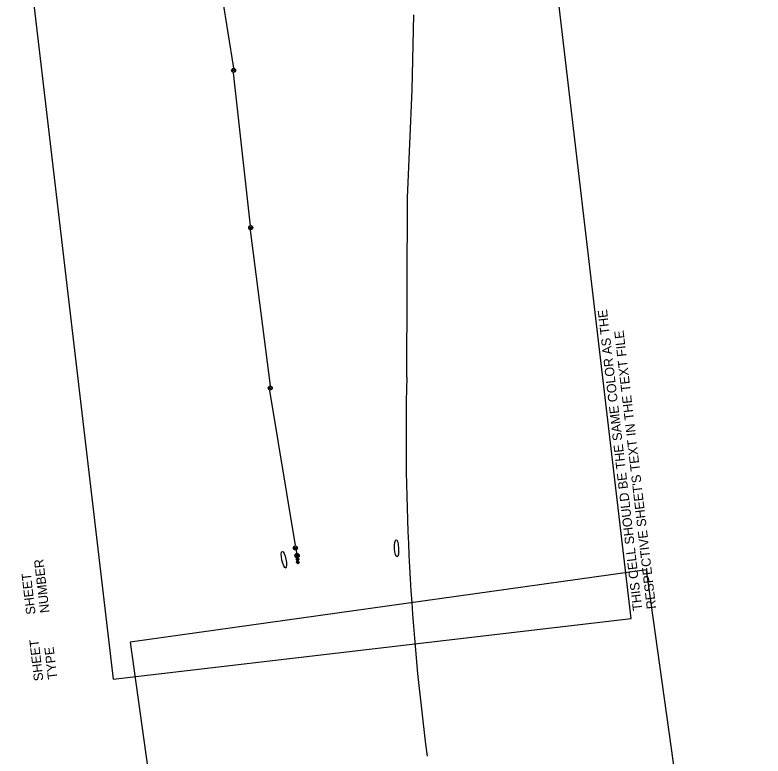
# Model space of a CAD drawing. Extents: x 601462 to 605493, y 331960 to 402715.
# Drawn here: x 602354 to 603753, y 385925 to 387311 of the extents above; entities that cross this region are included whole.
import ezdxf

# ---------------------------------------------------------------- set-up
doc = ezdxf.new("R2010")
doc.units = 0
for name, color, linetype in [('P_FTMS', 7, 'Continuous'), ('P_FTMSConduit', 7, 'Continuous'), ('P_MISC_TXT_1A (Construction)', 7, 'Continuous'), ('P_MISC_TXT_1B (Construction)', 7, 'Continuous')]:
    doc.layers.add(name, color=color, linetype=linetype)

# ---------------------------------------------------------------- blocks, each defined once
blk = doc.blocks.new('_U231')
at = {"layer": 'P_FTMS'}
for p, q in [((12.1, 1.6), (-12.2, -0.1)), ((11.8, 3), (-12.1, 1.4)), ((11.9, 2.3), (-12.1, 0.6)), ((12.1, 0.8), (-12.1, -0.8)), ((12.1, 0.1), (-12.1, -1.6)), ((11.6, 3.7), (-12, 2.1)), ((-11.9, 2.5), (-11.4, -4.2)), ((11.3, 4.4), (-11.8, 2.9)), ((11, 5.2), (-11.6, 3.6)), ((10.6, 5.9), (-11.4, 4.4)), ((-11.3, 4.5), (-10.6, -6)), ((10.2, 6.6), (-11, 5.1)), ((9.8, 7.3), (-10.7, 5.9)), ((-10.7, 5.9), (-9.8, -7.2)), ((9.2, 8), (-10.2, 6.6)), ((-10, 6.9), (-9, -8.2)), ((8.6, 8.6), (-9.7, 7.4)), ((-9.3, 7.8), (-8.2, -9)), ((7.8, 9.3), (-9, 8.2)), ((-8.6, 8.5), (-7.4, -9.6)), ((6.9, 10), (-8.2, 9)), ((-8, 9.2), (-6.6, -10.2)), ((-7.3, 9.7), (-5.9, -10.6)), ((5.8, 10.7), (-7.2, 9.8)), ((-6.6, 10.3), (-5.1, -11)), ((4.5, 11.3), (-6, 10.6)), ((-5.9, 10.7), (-4.4, -11.4)), ((-5.1, 11), (-3.6, -11.6)), ((-4.4, 11.3), (-2.9, -11.8)), ((2.5, 11.9), (-4.1, 11.5)), ((-3.7, 11.6), (-2.1, -12)), ((-3, 11.8), (-1.4, -12.1)), ((-2.3, 12), (-0.6, -12.2)), ((-1.6, 12.1), (0.1, -12.2)), ((-0.8, 12.1), (0.8, -12.1)), ((-0.1, 12.2), (1.6, -12.1)), ((0.6, 12.1), (2.3, -11.9)), ((1.4, 12.1), (3, -11.8)), ((2.1, 12), (3.7, -11.6)), ((2.9, 11.8), (4.4, -11.3)), ((3.6, 11.6), (5.1, -11)), ((4.4, 11.3), (5.9, -10.7)), ((5.1, 11), (6.6, -10.2)), ((5.9, 10.6), (7.3, -9.8)), ((6.6, 10.2), (8, -9.2)), ((7.4, 9.7), (8.6, -8.6)), ((8.2, 9), (9.3, -7.8)), ((9, 8.2), (10, -6.9)), ((9.8, 7.2), (10.7, -5.8)), ((10.6, 5.9), (11.3, -4.5)), ((11.5, 4), (11.9, -2.5)), ((12.1, -0.6), (-12, -2.3)), ((12.1, -1.4), (-11.8, -3)), ((12, -2.1), (-11.6, -3.7)), ((11.8, -2.9), (-11.3, -4.4)), ((11.6, -3.6), (-11, -5.1)), ((11.3, -4.4), (-10.7, -5.9)), ((11.1, -5.1), (-10.2, -6.6)), ((10.6, -5.9), (-9.8, -7.3)), ((10.2, -6.6), (-9.2, -8)), ((9.6, -7.4), (-8.5, -8.6)), ((9, -8.2), (-7.8, -9.3)), ((8.2, -9), (-6.9, -10)), ((7.3, -9.8), (-5.8, -10.7)), ((6, -10.6), (-4.5, -11.3)), ((4.1, -11.5), (-2.6, -11.9))]:
    blk.add_line(p, q, dxfattribs=at)
blk.add_circle((0, 0), 12.2, dxfattribs=at)
blk = doc.blocks.new('FMD')
at = {"layer": 'P_FTMS'}
for p, q in [((16.9, 17.6), (-16.9, 17.6)), ((-16.1, 16.1), (-16.1, 18.4)), ((16.1, 16.1), (-16.1, 16.1)), ((15.5, 19), (-15.5, 19)), ((-14.6, 14.6), (-14.6, 19.9)), ((14.6, 14.6), (-14.6, 14.6)), ((14, 20.5), (-14, 20.5)), ((-13.2, 13.2), (-13.2, 21.3)), ((13.2, 13.2), (-13.2, 13.2)), ((12.5, 21.9), (-12.5, 21.9)), ((-11.7, 11.7), (-11.7, 22.8)), ((11.7, 11.7), (-11.7, 11.7)), ((11.1, 23.4), (-11.1, 23.4)), ((-10.2, 10.2), (-10.2, 24.2)), ((10.2, 10.2), (-10.2, 10.2)), ((9.6, 24.9), (-9.6, 24.9)), ((-8.8, 8.8), (-8.8, 25.7)), ((8.8, 8.8), (-8.8, 8.8)), ((8.2, 26.3), (-8.2, 26.3)), ((-7.3, 7.3), (-7.3, 27.2)), ((7.3, 7.3), (-7.3, 7.3)), ((6.7, 27.8), (-6.7, 27.8)), ((-5.9, 5.9), (-5.9, 28.6)), ((5.9, 5.9), (-5.9, 5.9)), ((5.2, 29.3), (-5.2, 29.3)), ((-4.4, 4.4), (-4.4, 30.1)), ((4.4, 4.4), (-4.4, 4.4)), ((3.8, 30.7), (-3.8, 30.7)), ((-2.9, 2.9), (-2.9, 31.6)), ((2.9, 2.9), (-2.9, 2.9)), ((2.3, 32.2), (-2.3, 32.2)), ((-1.5, 1.5), (-1.5, 33)), ((1.5, 1.5), (-1.5, 1.5)), ((0.8, 33.6), (-0.8, 33.6)), ((0, 0), (0, 34.5)), ((1.5, 1.5), (1.5, 33)), ((2.9, 2.9), (2.9, 31.6)), ((4.4, 4.4), (4.4, 30.1)), ((5.9, 5.9), (5.9, 28.6)), ((7.3, 7.3), (7.3, 27.2)), ((8.8, 8.8), (8.8, 25.7)), ((10.2, 10.2), (10.2, 24.2)), ((11.7, 11.7), (11.7, 22.8)), ((13.2, 13.2), (13.2, 21.3)), ((14.6, 14.6), (14.6, 19.9)), ((16.1, 16.1), (16.1, 18.4))]:
    blk.add_line(p, q, dxfattribs=at)
blk.add_lwpolyline([(-17.2, 17.2), (0, 34.5), (17.2, 17.2), (0, 0)], close=True, dxfattribs=at)

msp = doc.modelspace()

# ---------------------------------------------------------------- linework, layer by layer
at = {"layer": 'P_FTMS'}
for centre in [(602763.2, 387207.5), (602795.1, 386913.4), (602831.5, 386613.3), (602878.6, 386314.3)]:
    msp.add_circle(centre, 3.75, dxfattribs=at)
for centre, start, end in [((602762.8, 387203), 32.6299, 138.8855), ((602763.5, 387212), 212.6299, 318.8855), ((602794.8, 386908.9), 32.6299, 138.8855), ((602795.5, 386917.9), 212.6299, 318.8855), ((602831.1, 386608.8), 32.6299, 138.8855), ((602831.8, 386617.8), 212.6299, 318.8855), ((602878.2, 386309.8), 32.6299, 138.8855), ((602878.9, 386318.8), 212.6299, 318.8855)]:
    msp.add_arc(centre, 3.75, start, end, dxfattribs=at)
for centre, major_axis in [((603067.9, 386313.7), (-0.9, 16)), ((602857.2, 386292.3), (-3.3, 15.6))]:
    msp.add_ellipse(centre, major_axis=major_axis, ratio=0.23471, dxfattribs=at)
at = {"layer": 'P_FTMSConduit'}
for p, q in [((602763.5, 387212), (602715.8, 387506.6)), ((602794.8, 386917.1), (602762.8, 387203)), ((602831.8, 386617.8), (602794.8, 386908.9)), ((602878.9, 386318.8), (602831.1, 386608.8)), ((602881.3, 386303.9), (602880.4, 386311))]:
    msp.add_line(p, q, dxfattribs=at)
msp.add_lwpolyline([(603086.8, 386633.3), (603088.1, 386969), (603097.2, 387171.1), (603099.9, 387311.3)], dxfattribs=at)
msp.add_arc((607629.3, 386522.9), 4543.8, 178.6075, 187.5611, dxfattribs=at)
at = {"layer": 'P_MISC_TXT_1A (Construction)'}
msp.add_lwpolyline([(603753.1, 384713.4), (603535, 386273.2), (602569.4, 386138.2), (602787.5, 384578.3)], close=True, dxfattribs=at)
msp.add_lwpolyline([(603753.1, 384713.4), (603535, 386273.2), (602569.4, 386138.2), (602787.5, 384578.3)], close=True, dxfattribs=at)
at = {"layer": 'P_MISC_TXT_1B (Construction)'}
msp.add_lwpolyline([(603506.3, 386182.5), (603322.6, 387746.8), (602354.3, 387633), (602538, 386068.8)], close=True, dxfattribs=at)
msp.add_lwpolyline([(603506.3, 386182.5), (603322.6, 387746.8), (602354.3, 387633), (602538, 386068.8)], close=True, dxfattribs=at)

# ---------------------------------------------------------------- block references
at = {"layer": 'P_FTMS'}
for name, p, xscale, yscale, rotation in [('_U231', (602881.8, 386300), 0.32808333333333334, 0.3280833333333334, -173.19817986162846), ('FMD', (602885.5, 386293.4), 0.16404166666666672, 0.1640416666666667, 92.69468437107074), ('FMD', (602885.8, 386287.7), 0.16404166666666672, 0.1640416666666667, 92.69468437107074)]:
    msp.add_blockref(name, p, dxfattribs=dict(at, xscale=xscale, yscale=yscale, rotation=rotation))

# ---------------------------------------------------------------- texts
at = {"layer": 'P_MISC_TXT_1B (Construction)'}
for s, p in [('THIS CELL SHOULD BE THE SAME COLOR AS THE', (603527.3, 386198)), ('THIS CELL SHOULD BE THE SAME COLOR AS THE', (603527.3, 386198)), ("RESPECTIVE SHEET'S TEXT IN THE TEXT FILE", (603553.3, 386201.1)), ("RESPECTIVE SHEET'S TEXT IN THE TEXT FILE", (603553.3, 386201.1)), ('NUMBER', (602419, 386193.7)), ('NUMBER', (602419, 386193.7)), ('SHEET', (602392.9, 386190.7)), ('SHEET', (602392.9, 386190.7)), ('SHEET', (602407.5, 386066.5)), ('SHEET', (602407.5, 386066.5)), ('TYPE', (602433.5, 386069.6)), ('TYPE', (602433.5, 386069.6))]:
    msp.add_text(s, height=17.5, rotation=96.6981, dxfattribs=at).set_placement(p)

doc.saveas('drawing.dxf')
